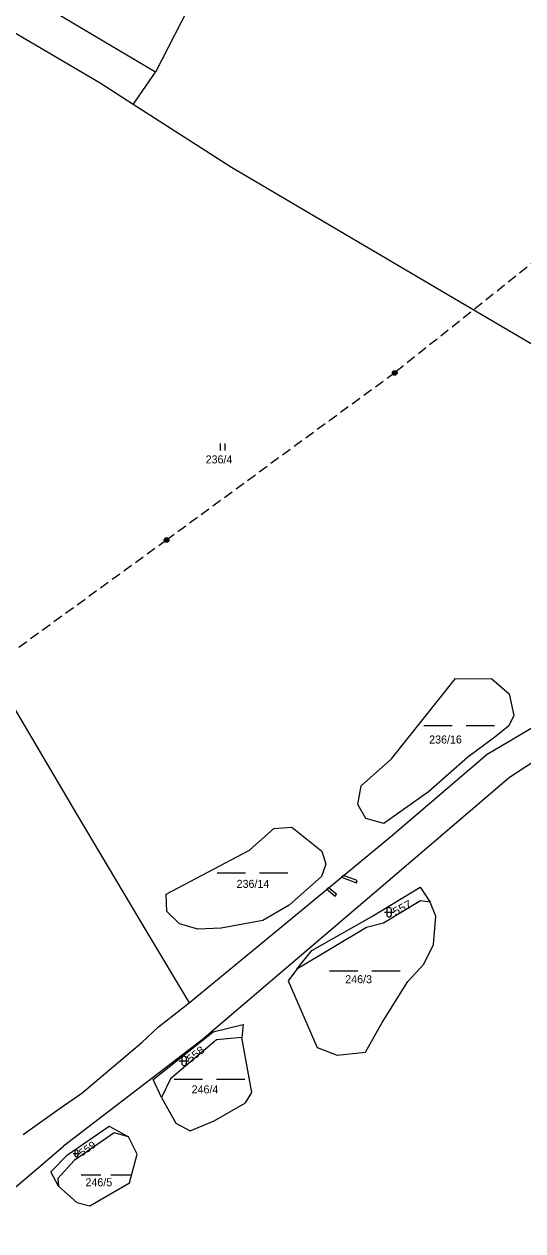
# Model space of a CAD drawing. Extents: x -885985 to -883535, y -1030025 to -1027941.
# Drawn here: x -884528.7 to -884422.7, y -1028556.2 to -1028299.8 of the extents above; entities that cross this region are included whole.
import ezdxf
from ezdxf.enums import TextEntityAlignment as Align

# ---------------------------------------------------------------- set-up
doc = ezdxf.new("R2010")
doc.units = 0
doc.header["$LTSCALE"] = 0.68
doc.linetypes.add('MEDIUM_DASHED', pattern=[4.5, 3, -1.5])
for name, color, linetype, lineweight in [('1', 7, 'Continuous', 25), ('13', 7, 'Continuous', 13), ('3', 7, 'Continuous', 25), ('6', 7, 'Continuous', 25)]:
    doc.layers.add(name, color=color, linetype=linetype, lineweight=lineweight)
doc.layers.add('2', color=7, linetype='Continuous')

msp = doc.modelspace()

# ---------------------------------------------------------------- linework, layer by layer
at = {"layer": '1'}
for p, q in [((-884414.76, -1028141.6), (-884500.76, -1028310.05)), ((-884500.76, -1028310.05), (-884573.54, -1028266.88)), ((-884512.54, -1028312.41), (-884580.94, -1028272.18)), ((-884505.53, -1028316.9), (-884500.76, -1028310.05)), ((-884505.53, -1028316.9), (-884512.54, -1028312.41)), ((-884484.62, -1028330.29), (-884505.53, -1028316.9)), ((-884432.41, -1028361.04), (-884484.62, -1028330.29)), ((-884348.51, -1028410.11), (-884432.41, -1028361.04)), ((-884450.63, -1028455.92), (-884437.02, -1028438.85)), ((-884437.02, -1028438.85), (-884429.25, -1028438.96)), ((-884429.25, -1028438.96), (-884425.6, -1028442.11)), ((-884425.6, -1028442.11), (-884424.6, -1028446.71)), ((-884531.74, -1028443.62), (-884517.46, -1028467.79)), ((-884430.24, -1028454.93), (-884412.49, -1028444.45)), ((-884424.6, -1028446.71), (-884425.67, -1028448.89)), ((-884425.67, -1028448.89), (-884428.67, -1028451.34)), ((-884428.67, -1028451.34), (-884434.39, -1028455.6)), ((-884450.76, -1028472.41), (-884430.24, -1028454.93)), ((-884415.83, -1028453.58), (-884425.5, -1028459.92)), ((-884457.08, -1028461.67), (-884450.63, -1028455.92)), ((-884434.39, -1028455.6), (-884442.75, -1028462.91)), ((-884425.5, -1028459.92), (-884451.36, -1028481.96)), ((-884457.77, -1028465.64), (-884457.08, -1028461.67)), ((-884442.75, -1028462.91), (-884452.2, -1028469.7)), ((-884517.46, -1028467.79), (-884502.62, -1028492.76)), ((-884456.07, -1028468.6), (-884457.77, -1028465.64)), ((-884475.61, -1028470.73), (-884471.79, -1028470.44)), ((-884471.79, -1028470.44), (-884465.44, -1028475.56)), ((-884452.2, -1028469.7), (-884456.07, -1028468.6)), ((-884480.77, -1028475.37), (-884475.61, -1028470.73)), ((-884473.16, -1028490.9), (-884450.76, -1028472.41)), ((-884498.48, -1028484.71), (-884480.77, -1028475.37)), ((-884465.44, -1028475.56), (-884464.57, -1028478.3)), ((-884464.57, -1028478.3), (-884465.49, -1028480.94)), ((-884465.49, -1028480.94), (-884472.32, -1028487.01)), ((-884451.36, -1028481.96), (-884490.85, -1028515.62)), ((-884454.75, -1028489.41), (-884444.53, -1028483.18)), ((-884444.53, -1028483.18), (-884442.38, -1028486.4)), ((-884498.38, -1028488.34), (-884498.48, -1028484.71)), ((-884472.32, -1028487.01), (-884477.92, -1028490.26)), ((-884444.43, -1028486.1), (-884452.29, -1028490.83)), ((-884442.38, -1028486.4), (-884444.43, -1028486.1)), ((-884441.2, -1028489.38), (-884442.38, -1028486.4)), ((-884493.63, -1028507.74), (-884473.16, -1028490.9)), ((-884477.92, -1028490.26), (-884486.79, -1028491.92)), ((-884467.56, -1028496.66), (-884454.75, -1028489.41)), ((-884452.29, -1028490.83), (-884455.91, -1028491.8)), ((-884441.69, -1028495.4), (-884441.2, -1028489.38)), ((-884502.62, -1028492.76), (-884493.63, -1028507.74)), ((-884486.79, -1028491.92), (-884491.76, -1028492.11)), ((-884455.91, -1028491.8), (-884470.73, -1028500.62)), ((-884443.71, -1028499.53), (-884441.69, -1028495.4)), ((-884470.73, -1028500.62), (-884467.56, -1028496.66)), ((-884470.73, -1028500.62), (-884472.59, -1028503.13)), ((-884447.16, -1028503.23), (-884443.71, -1028499.53)), ((-884472.59, -1028503.13), (-884466.39, -1028517.29)), ((-884452.56, -1028511.95), (-884447.16, -1028503.23)), ((-884500.1, -1028512.86), (-884493.63, -1028507.74)), ((-884503.57, -1028516.1), (-884500.1, -1028512.86)), ((-884501.27, -1028524.08), (-884488.51, -1028513.94)), ((-884488.51, -1028513.94), (-884482.12, -1028512.39)), ((-884482.12, -1028512.39), (-884482.38, -1028515.14)), ((-884456.16, -1028518.27), (-884452.56, -1028511.95)), ((-884490.85, -1028515.62), (-884520.3, -1028538.19)), ((-884505.89, -1028518.06), (-884503.57, -1028516.1)), ((-884487.79, -1028515.66), (-884497.56, -1028523.9)), ((-884482.38, -1028515.14), (-884487.79, -1028515.66)), ((-884480.31, -1028526.84), (-884482.38, -1028515.14)), ((-884516.44, -1028526.96), (-884505.89, -1028518.06)), ((-884466.39, -1028517.29), (-884462.17, -1028518.89)), ((-884462.17, -1028518.89), (-884456.16, -1028518.27)), ((-884499.52, -1028527.92), (-884501.27, -1028524.08)), ((-884497.56, -1028523.9), (-884499.52, -1028527.92)), ((-884521.21, -1028530.3), (-884516.44, -1028526.96)), ((-884481.63, -1028529.05), (-884480.31, -1028526.84)), ((-884499.52, -1028527.92), (-884496.47, -1028533.33)), ((-884488.27, -1028532.84), (-884481.63, -1028529.05)), ((-884528.9, -1028535.72), (-884521.21, -1028530.3)), ((-884519.49, -1028540.1), (-884510.63, -1028534.01)), ((-884510.63, -1028534.01), (-884506.52, -1028536.24)), ((-884496.47, -1028533.33), (-884493.4, -1028535)), ((-884493.4, -1028535), (-884488.27, -1028532.84)), ((-884509.54, -1028535.38), (-884518.04, -1028541.27)), ((-884506.52, -1028536.24), (-884509.54, -1028535.38)), ((-884504.63, -1028539.92), (-884506.52, -1028536.24)), ((-884541.49, -1028556.22), (-884520.3, -1028538.19)), ((-884506.3, -1028546.02), (-884504.63, -1028539.92)), ((-884522.99, -1028543.66), (-884519.49, -1028540.1)), ((-884518.04, -1028541.27), (-884521.51, -1028545.07)), ((-884521.36, -1028546.73), (-884522.99, -1028543.66)), ((-884521.51, -1028545.07), (-884521.36, -1028546.73)), ((-884521.36, -1028546.73), (-884517.51, -1028550.17)), ((-884514.72, -1028550.93), (-884506.3, -1028546.02)), ((-884517.51, -1028550.17), (-884514.72, -1028550.93))]:
    msp.add_line(p, q, dxfattribs=at)
msp.add_lwpolyline([(-884491.76, -1028492.11), (-884495.63, -1028491.02), (-884498.38, -1028488.34)], dxfattribs=at)
at = {"layer": '13'}
for points in [[(-884458.07, -1028482.27), (-884457.91, -1028481.8), (-884460.8, -1028480.7), (-884461.24, -1028481.06)], [(-884463.97, -1028483.32), (-884464.37, -1028483.64), (-884462.61, -1028485.08), (-884462.3, -1028484.68)]]:
    msp.add_lwpolyline(points, close=True, dxfattribs=at)
at = {"layer": '3'}
for p, q in [((-884486.931, -1028390.41), (-884486.931, -1028388.91)), ((-884485.93, -1028390.41), (-884485.93, -1028388.91)), ((-884443.719, -1028448.88), (-884437.719, -1028448.88)), ((-884434.719, -1028448.88), (-884428.719, -1028448.88)), ((-884487.629, -1028480.18), (-884481.629, -1028480.18)), ((-884478.629, -1028480.18), (-884472.629, -1028480.18)), ((-884452.121, -1028488.531), (-884450.119, -1028488.531)), ((-884451.621, -1028488.031), (-884451.621, -1028489.032)), ((-884450.619, -1028489.032), (-884450.619, -1028488.031)), ((-884463.789, -1028500.94), (-884457.789, -1028500.94)), ((-884454.789, -1028500.94), (-884448.789, -1028500.94)), ((-884495.701, -1028520.111), (-884493.699, -1028520.111)), ((-884495.201, -1028519.611), (-884495.201, -1028520.612)), ((-884494.199, -1028520.612), (-884494.199, -1028519.611)), ((-884496.789, -1028524), (-884490.789, -1028524)), ((-884487.789, -1028524), (-884481.789, -1028524)), ((-884518.261, -1028539.771), (-884516.859, -1028539.771)), ((-884517.91, -1028539.42), (-884517.91, -1028540.121)), ((-884517.21, -1028540.121), (-884517.21, -1028539.42)), ((-884516.573, -1028544.3), (-884512.373, -1028544.3)), ((-884510.272, -1028544.3), (-884506.072, -1028544.3))]:
    msp.add_line(p, q, dxfattribs=at)
for centre, radius, start, end in [((-884451.12, -1028488.0309), 0.5, 0, 180), ((-884451.12, -1028489.0309), 0.5, 180, 359.98789), ((-884494.7, -1028519.6109), 0.5, 0, 180), ((-884494.7, -1028520.6109), 0.5, 180, 359.98789), ((-884517.56, -1028539.4206), 0.35, 0, 180), ((-884517.56, -1028540.1206), 0.35, 180, 359.98789)]:
    msp.add_arc(centre, radius, start, end, dxfattribs=at)
at = {"layer": '6', "linetype": 'MEDIUM_DASHED'}
for p, q in [((-884397.9, -1028332.33), (-884449.91, -1028373.93)), ((-884449.91, -1028373.93), (-884498.42, -1028409.47)), ((-884498.42, -1028409.47), (-884561.98, -1028455.63))]:
    msp.add_line(p, q, dxfattribs=at)
at = {"layer": '6'}
for centre, radius in [((-884449.9134, -1028373.9299), 0.5), ((-884449.9134, -1028373.9299), 0.4), ((-884449.9134, -1028373.9299), 0.3), ((-884449.9134, -1028373.9299), 0.2), ((-884449.9134, -1028373.9299), 0.1), ((-884498.4234, -1028409.4699), 0.5), ((-884498.4234, -1028409.4699), 0.4), ((-884498.4234, -1028409.4699), 0.3), ((-884498.4234, -1028409.4699), 0.2), ((-884498.4234, -1028409.4699), 0.1)]:
    msp.add_circle(centre, radius, dxfattribs=at)

# ---------------------------------------------------------------- texts
at = {"layer": '2'}
for s, p in [('236/4', (-884490.11, -1028393.165)), ('246/3', (-884460.43, -1028503.605)), ('246/4', (-884493.09, -1028527.005)), ('246/5', (-884515.65, -1028546.745))]:
    msp.add_text(s, height=1.7, dxfattribs=at).set_placement(p)
for s, p in [('236/16', (-884439.12, -1028452.675)), ('236/14', (-884480.05, -1028483.345))]:
    msp.add_text(s, height=1.7, dxfattribs=at).set_placement(p, align=Align.CENTER)
for s, height, rotation, width, p in [('557', 1.7, 28, 1.1, (-884449.78, -1028489.315)), ('558', 1.6, 38, 1.15, (-884493.383, -1028520.595)), ('559', 1.5, 35, 1.15, (-884516.434, -1028540.467))]:
    msp.add_text(s, height=height, rotation=rotation, dxfattribs=dict(at, width=width)).set_placement(p)

doc.saveas('drawing.dxf')
